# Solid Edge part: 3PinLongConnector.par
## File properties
Author: conerly
Template: Ansi Part.par
Last saved by: alogan
Revision: 22
Application: Solid Edge
Density: 0.0979772159 lbm/in^3
Accuracy: 0.990
Material: Aluminum, 1060
Face Style: Aluminum
Fill Style: ANSI38(Aluminum)
Virtual Style: Polished aluminum
Coef. of Thermal Exp: 2.3e-05
Thermal Conductivity: 221.0
Specific Heat: 920.0
Modulus of Elasticity: 68947570000.0
Poisson's Ratio: 0.33
Yield Stress: 27579028.0
Ultimate Stress: 68947570.0
Elongation: 0.0
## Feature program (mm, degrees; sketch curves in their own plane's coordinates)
sketch for "unnamed Protrusion 1" plane through (10.8687, 10.8687, 0) normal (0, 0, 1) x-axis (1, 0, 0)
  line (-10.8687, -10.8687) -> (-4.5187, -10.8687)
  line (-4.5187, -10.8687) -> (-4.5187, 1.8313)
  line (-4.5187, 1.8313) -> (1.8313, 1.8313)
  line (1.8313, 1.8313) -> (1.8313, 14.5313)
  line (1.8313, 14.5313) -> (8.1813, 14.5313)
  line (8.1813, 14.5313) -> (8.1813, 27.2313)
  line (8.1813, 27.2313) -> (-10.8687, 27.2313)
  line (-10.8687, 27.2313) -> (-10.8687, -10.8687)
  dimension (linear) = 4.5187
  dimension (linear) = 1.8313
  dimension (linear) = 8.1813
  dimension (linear) = 10.8687
extrude "unnamed Protrusion 1" add finite 6.35 symmetric
sketch for "ExtrudedCutout_1" plane through (3.175, 0, 0) normal (0, -1, 0) x-axis (1, 0, 0)
  circle centre (0, 0) radius 1.27
extrude "ExtrudedCutout_1" cut finite 1.524 along -normal
sketch for "ExtrudedCutout_2" plane through (9.3638, 12.7, -0.0457) normal (0, -1, 0) x-axis (1, 0, 0)
  circle centre (0.1612, 0.0457) radius 1.27
extrude "ExtrudedCutout_2" cut finite 1.524 along -normal
sketch for "ExtrudedCutout_3" plane through (15.8086, 25.4, -0.1934) normal (0, -1, 0) x-axis (1, 0, 0)
  circle centre (0.0664, 0.1934) radius 1.27
extrude "ExtrudedCutout_3" cut finite 1.524 along -normal
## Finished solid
Body 1: solid body, 16 faces, 30 edges, 16 vertices.
  Faces by surface: plane 13, cylinder 3
  Edges by curve: line 24, circle 6
Bounding box of the edges (mm): 19.050 x 38.100 x 6.350, from (0, 0, -3.175) to (19.05, 38.1, 3.175).
Cylindrical faces by radius (mm): R1.27 x3
Planar faces by outward normal: +x 3, +y 1, +z 1, -x 1, -y 6, -z 1
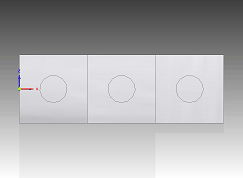
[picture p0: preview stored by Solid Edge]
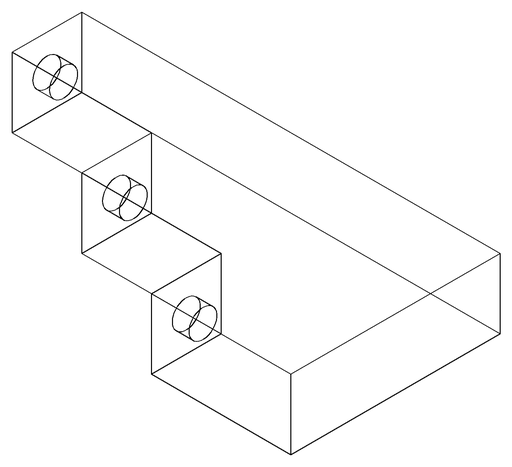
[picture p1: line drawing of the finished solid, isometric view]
